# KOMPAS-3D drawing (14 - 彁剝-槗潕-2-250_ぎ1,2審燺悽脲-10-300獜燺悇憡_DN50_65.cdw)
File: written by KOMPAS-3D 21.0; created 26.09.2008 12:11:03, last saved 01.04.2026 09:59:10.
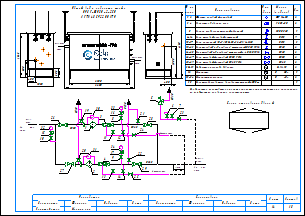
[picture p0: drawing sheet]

Sheets 1-2: A3, landscape

Document properties: Наименование: Макро:21; Автор: RaskoAdmin; Форматы листов документа: 2xA3; Полное имя файла: \\UR38nt01\Departments\КТО\КБ ПУРДГ\Заявки\Прайс-лист на типовые шкафы ГРПШ\ПРДГ_стандарт_20_03_2026\ПРДГ с РДСК\ПРДГ-ШУЭО-2-250_до1,2МПа_Рвых-10-300кПа_РДСК_DN50_65.cdw

Title block, sheet 1: Наименование: Пункт учета газа / ПУГ-Ш-400-Р / ЛГТИ.485922.001ТУ; designation: ЛГТИ.03.4411141; sheet number: 1; Количество листов документа: 2; organisation: ООО "ЭЛЬСТЕР Газэлектроника"; Форматы листов документа: A3; stored path: C:\Рабочие документы\Компас\ПУГ\Схема.cdw; Разработал: Устинов; Проверил: Кошкин; Утвердил: Кошкин
Title block, sheet 2: sheet number: 2; stored path: D:\Рабочие документы\Заявки\ПУРДГ\ПУРДГ-ШУЭО-2-100-Р 4411220.cdw; designation, second copy: ЛГТИ.03.4411141-

Views: Вид 1, Вид 2
Referenced files: wcvoit.frw
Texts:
  Normal
  Вход
  газа
  PDI
  Выход
  Р=     кПа
  DN65
  DN50
  DN20
  Импульс DN20
  ≥5DN
  HYSWLongFangSong
  № на
  схеме
  Усл.
  обозн.
  Марка
  (модель)
  Кол.
  Фильтр газовый фланцевый
  ФГ 16-50
  Регулятор давления газа
  РДCК-50
  Клапан предохранительный сбросной
  КПС DN20
  Кран шаровой газовый латунный
  DN15
  Кран кнопочный VE-РАСКО-НЗ-1,6-G1/2-М20
  Кран шаровой "под приварку" штуцерный DN20 PN16
  Кран шаровой "под приварку" штуцерный п/п DN20 PN16
  Кран шаровой фланцевый DN50 PN16
  Кран шаровой фланцевый DN65 PN16
  Индикатор перепада давления
  Delta 15
  Манометр
  Манометр-напоромер
  Электрообогреватель взрывозащищенный 400Вт
  0...     МПа
  0...     кПа
  Общий вид и габариты шкафа
  ПРДГ-ШУЭО-2-250
  Выход газа
  Вход газа
  Схема открывания дверей
  Р=        МПа
  logo-rasko-ge.png
  Предприятие изготовитель может заменять комплектующие на аналогичные,
  не ухудшающие заявленных характеристик.
  Должность
  Конструктор
  Фамилия
  Подпись
  Дата
  Согласовано
  Максимкин
  Лист
  Листов
  POLYLINE_STYLE_0.18_RGB_0_0_0
  POLYLINE_STYLE_0.50_RGB_0_0_0
  POLYLINE_STYLE_0.34_RGB_0_0_0
  PHANTOM_RGB_0_0_0_SC_1_THICK_0.18
  K5LT_THIN_RGB_0_0_0_THICK_0.18
  K5LT32769_RGB_0_0_0_THICK_0.18
  K5LT12_RGB_0_0_0_SC_1_THICK_0.18
  K5LT_DASHED_RGB_0_0_0_SC_1_THICK_0.18
  ACISOTGL_RGB_0_0_0_SC_0.8_THICK_0.25
  CONTINUOUS_RGB_0_127_31_THICK_0.3
  CONTINUOUS_RGB_0_0_255_THICK_0.35
  CONTINUOUS_RGB_255_0_0_THICK_0.35
  POLYLINE_STYLE_0.25_RGB_0_0_0
  CONTINUOUS_RGB_0_0_0_THICK_0.5
  POLYLINE_STYLE_0.35_RGB_0_0_255
  CONTINUOUS_RGB_0_0_0_THICK_0.4
  CONTINUOUS_RGB_0_0_0_THICK_0.35
  Без оформления
Dimensions and other numbers on the sheet: 1; 2; 3; 4; 5; 10; 27; 28; 29; 23; 8; 12; 19; 20; 21; 22; 25; 24; 30; 31; 15; 16; 26; 6; 7; 11; 14; 13; 33; 1, 2; 3, 4; 6-14; 9; 15-17; 18-23; 24-25; 26-27; 28-29; 30-31; 32; 33-34; 35; 400; 1050; 500; 305; 2300; 1565; 2600; 17; 34; 1000; 4130; 18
